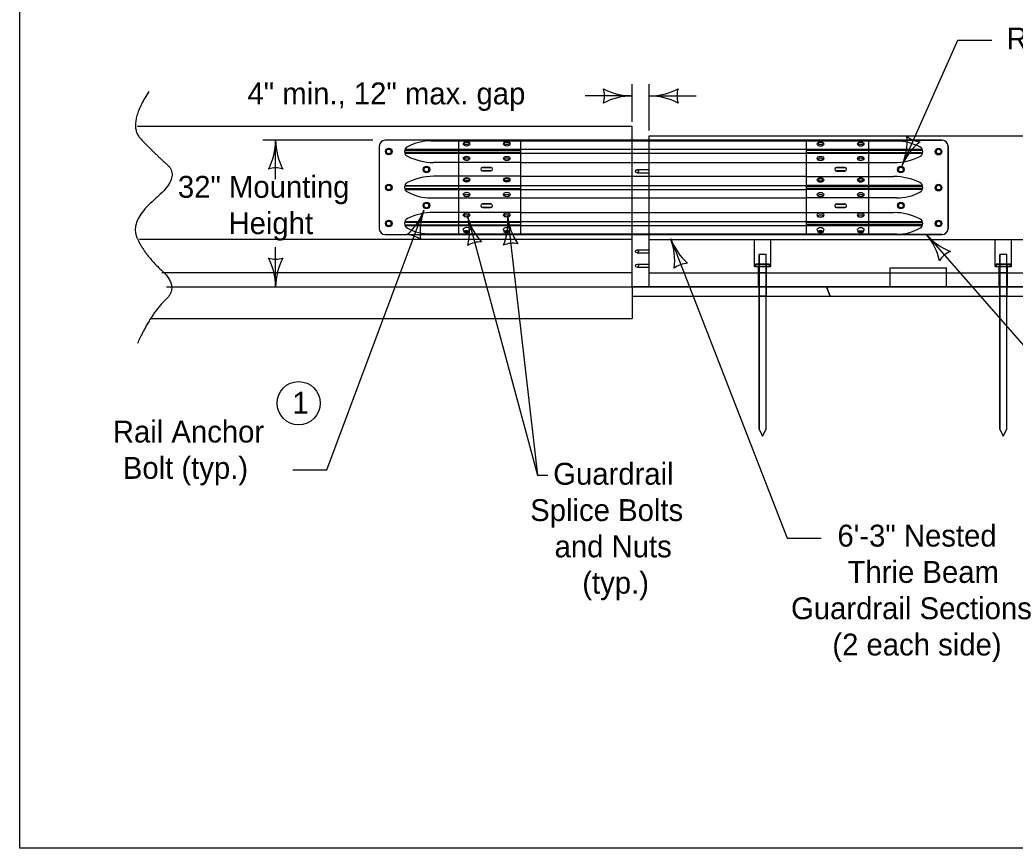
# Model space of a CAD drawing. Extents: x 10028 to 81668, y 3581 to 11018.
# Drawn here: x 13733 to 14423, y 7924 to 8499 of the extents above; entities that cross this region are included whole.
import ezdxf

# ---------------------------------------------------------------- set-up
doc = ezdxf.new("R2010")
doc.units = 0
for name, color, linetype in [('conPaving', 7, 'Continuous'), ('dsnCellsNorthArrow', 7, 'Continuous'), ('dsnTextTabulation', 7, 'Continuous'), ('Level 41', 7, 'Continuous'), ('Level 9', 7, 'Continuous'), ('SheetBorder', 7, 'Continuous')]:
    doc.layers.add(name, color=color, linetype=linetype)

msp = doc.modelspace()

# ---------------------------------------------------------------- linework, layer by layer
at = {"layer": 'conPaving'}
for p, q in [((14080.33, 8415.38), (13986.12, 8415.38)), ((14278.57, 8415.38), (14080.33, 8415.38)), ((14372.78, 8415.38), (14278.57, 8415.38)), ((13982.02, 8411.28), (13982.02, 8353.94)), ((14376.88, 8353.94), (14376.88, 8411.28)), ((14053.7, 8396.54), (14059.44, 8396.54)), ((14299.46, 8396.54), (14305.2, 8396.54)), ((14059.44, 8394.08), (14053.7, 8394.08)), ((14305.2, 8394.08), (14299.46, 8394.08)), ((14053.7, 8371.14), (14059.44, 8371.14)), ((14059.44, 8368.68), (14053.7, 8368.68)), ((14299.46, 8371.14), (14305.2, 8371.14)), ((14305.2, 8368.68), (14299.46, 8368.68)), ((13986.12, 8349.84), (14080.33, 8349.84)), ((14080.33, 8349.84), (14278.57, 8349.84)), ((14278.57, 8349.84), (14372.78, 8349.84)), ((14245.28, 8313.61), (14159.64, 8313.61)), ((14245.65, 8313.61), (14245.28, 8313.61)), ((14245.65, 8307.05), (14245.65, 8313.61)), ((14250.94, 8313.61), (14250.57, 8313.61)), ((14250.57, 8313.61), (14250.57, 8307.05)), ((14292.58, 8313.61), (14250.94, 8313.61)), ((14292.58, 8313.61), (14295.13, 8307.05)), ((14295.13, 8307.05), (14292.58, 8313.61)), ((14412.77, 8307.05), (14412.77, 8313.61)), ((14418.06, 8313.61), (14417.68, 8313.61)), ((14417.68, 8313.61), (14417.68, 8307.05)), ((14157.59, 8307.05), (14157.59, 8307.05)), ((14157.59, 8307.05), (14157.59, 8307.05)), ((14157.59, 8307.05), (14245.65, 8307.05)), ((14250.57, 8307.05), (14295.13, 8307.05)), ((14295.13, 8307.05), (14412.77, 8307.05)), ((14417.68, 8307.05), (14579.89, 8307.05))]:
    msp.add_line(p, q, dxfattribs=at)
for points in [[(14159.64, 8313.61), (14157.59, 8313.61), (14157.59, 8307.05)], [(14412.77, 8313.61), (14412.4, 8313.61), (14375.91, 8313.61), (14336.58, 8313.61), (14292.58, 8313.61)], [(14493.87, 8313.61), (14454.55, 8313.61), (14418.06, 8313.61)]]:
    msp.add_lwpolyline(points, dxfattribs=at)
for centre, radius, start, end in [((13986.12, 8411.28), 4.1, 90, 180), ((14372.78, 8411.28), 4.1, 0, 90), ((14053.7, 8395.31), 1.23, 90, 270), ((14059.44, 8395.31), 1.23, 270, 90), ((14299.46, 8395.31), 1.23, 90, 270), ((14305.2, 8395.31), 1.23, 270, 90), ((14053.7, 8369.91), 1.23, 90, 270), ((14059.44, 8369.91), 1.23, 270, 90), ((14299.46, 8369.91), 1.23, 90, 270), ((14305.2, 8369.91), 1.23, 270, 90), ((13986.12, 8353.94), 4.1, 180, 270), ((14372.78, 8353.94), 4.1, 270, 0)]:
    msp.add_arc(centre, radius, start, end, dxfattribs=at)
at = {"layer": 'dsnCellsNorthArrow'}
msp.add_line((14157.59, 8313.61), (14157.59, 8425.02), dxfattribs=at)
at = {"layer": 'dsnTextTabulation'}
for p, q in [((14344.94, 8397.87), (14383.72, 8484.78)), ((14383.72, 8484.78), (14407.32, 8484.78)), ((14157.59, 8428.24), (14157.59, 8454.2)), ((14169.47, 8422.14), (14169.47, 8454.2)), ((14157.59, 8446.16), (14125.02, 8446.16)), ((14169.47, 8446.16), (14202.03, 8446.16)), ((13977.54, 8415.38), (13901.17, 8415.38)), ((13910.06, 8388.43), (13910.06, 8415.38)), ((14169.47, 8313.85), (14169.47, 8418.46)), ((14169.47, 8418.46), (14660.99, 8418.46)), ((13945.69, 8186.49), (14013.03, 8366.86)), ((14043.27, 8362.89), (14091.8, 8182.83)), ((14071.11, 8362.89), (14091.8, 8182.83)), ((14169.47, 8346.37), (14660.99, 8346.37)), ((14184.39, 8346.97), (14265.14, 8139.23)), ((14361.76, 8350.15), (14525.96, 8161.81)), ((13910.06, 8313.61), (13910.06, 8341.06)), ((14336.58, 8326.71), (14375.91, 8326.71)), ((14169.47, 8323.44), (14660.99, 8323.44)), ((14336.58, 8313.61), (14336.58, 8323.44)), ((14375.91, 8313.61), (14375.91, 8323.44)), ((14169.71, 8313.61), (14336.58, 8313.61)), ((14375.91, 8313.61), (14454.55, 8313.61)), ((13922.09, 8186.49), (13945.69, 8186.49)), ((14091.8, 8182.83), (14099.09, 8182.83)), ((14265.14, 8139.23), (14288.74, 8139.23))]:
    msp.add_line(p, q, dxfattribs=at)
msp.add_circle((13926.02, 8232.83), 15, dxfattribs=at)
for centre, radius, start, end in [((14121.95, 8446.16), 16.42, 342.26665, 17.73335), ((14157.59, 8488.66), 42.5, 241.92751, 270), ((14121.95, 8446.16), 16.42, 342.26665, 17.73335), ((14157.59, 8488.66), 42.5, 241.92751, 270), ((14169.47, 8488.66), 42.5, 270, 298.07249), ((14169.47, 8488.66), 42.5, 270, 298.07249), ((14205.1, 8446.16), 16.42, 162.26665, 197.73335), ((14205.1, 8446.16), 16.42, 162.26665, 197.73335), ((14157.59, 8403.66), 42.5, 90, 118.07249), ((14157.59, 8403.66), 42.5, 90, 118.07249), ((14169.47, 8403.66), 42.5, 61.92751, 90), ((14169.47, 8403.66), 42.5, 61.92751, 90), ((13867.56, 8415.38), 42.5, 331.92751, 360), ((13952.56, 8415.38), 42.5, 180, 208.07249), ((14305.93, 8414.75), 42.5, 336.60184, 4.67433), ((14359.09, 8430.58), 16.42, 228.86849, 264.33519), ((14383.94, 8381), 42.5, 128.52935, 156.60184), ((13910.06, 8379.74), 16.42, 72.26665, 107.73335), ((13973.22, 8381.73), 42.5, 311.45357, 339.52606), ((14052.85, 8352), 42.5, 159.52606, 187.59855), ((14002.11, 8352.29), 42.5, 346.36285, 14.43534), ((14084.43, 8373.48), 42.5, 194.43534, 222.50783), ((14028.83, 8358.52), 42.5, 337.83385, 5.90634), ((14113.38, 8367.27), 42.5, 185.90634, 213.97883), ((14000.57, 8333.48), 16.42, 51.79271, 87.25941), ((14144.6, 8332.02), 42.5, 352.52075, 20.59324), ((14224.17, 8361.92), 42.5, 200.59324, 228.66573), ((14329.41, 8322.59), 42.5, 12.36113, 40.43362), ((14394.11, 8377.71), 42.5, 220.43362, 248.50611), ((14052.15, 8328.37), 16.42, 86.70199, 122.16869), ((14074.78, 8327.45), 16.42, 78.17299, 113.63969), ((13910.06, 8349.24), 16.42, 252.26665, 287.73335), ((13867.56, 8313.61), 42.5, 360, 28.07249), ((13952.56, 8313.61), 42.5, 151.92751, 180), ((14384.87, 8323.03), 16.42, 112.70027, 148.16697), ((14196.92, 8313.61), 16.42, 92.85989, 128.32659)]:
    msp.add_arc(centre, radius, start, end, dxfattribs=at)
at = {"layer": 'Level 41'}
for p, q in [((14160.96, 8394.95), (14169.47, 8394.95)), ((14160.96, 8392.83), (14169.47, 8392.83)), ((14242.45, 8327.81), (14242.45, 8346.37)), ((14253.77, 8327.81), (14253.77, 8346.37)), ((14409.56, 8327.81), (14409.56, 8346.37)), ((14420.89, 8327.81), (14420.89, 8346.37)), ((14160.96, 8339.24), (14169.46, 8339.24)), ((14160.96, 8337.12), (14169.46, 8337.12)), ((14160.96, 8329.41), (14169.46, 8329.41)), ((14160.96, 8327.29), (14169.46, 8327.29)), ((14242.45, 8327.81), (14253.77, 8327.81)), ((14245.28, 8313.61), (14245.28, 8327.81)), ((14250.94, 8313.61), (14250.94, 8327.81)), ((14409.56, 8327.81), (14420.89, 8327.81)), ((14412.4, 8313.61), (14412.4, 8327.81)), ((14418.06, 8313.61), (14418.06, 8327.81))]:
    msp.add_line(p, q, dxfattribs=at)
for centre in [(14160.96, 8393.89), (14160.96, 8338.18), (14160.96, 8328.35)]:
    msp.add_circle(centre, 1.06, dxfattribs=at)
at = {"layer": 'Level 9'}
for p, q in [((14157.59, 8425.02), (13814.19, 8425.02)), ((14080.33, 8415.38), (13986.12, 8415.38)), ((14080.33, 8415.38), (13986.12, 8415.38)), ((14036.91, 8415.38), (14036.91, 8349.84)), ((14080.33, 8349.84), (14080.33, 8415.38)), ((14278.57, 8415.38), (14372.78, 8415.38)), ((14278.57, 8349.84), (14278.57, 8415.38)), ((14321.99, 8349.73), (14321.99, 8415.27)), ((13982.02, 8411.28), (13982.02, 8353.94)), ((13982.02, 8411.28), (13982.02, 8353.94)), ((13999.63, 8408.46), (14080.33, 8408.46)), ((13999.86, 8409.08), (14080.33, 8409.08)), ((14359.04, 8408.96), (14278.57, 8408.96)), ((14359.26, 8408.35), (14278.57, 8408.35)), ((14376.88, 8411.28), (14376.88, 8353.94)), ((14376.88, 8411.28), (14376.88, 8353.94)), ((14080.33, 8406.93), (13999.56, 8406.93)), ((13999.73, 8406.32), (14080.33, 8406.32)), ((14278.57, 8406.82), (14359.33, 8406.82)), ((14359.17, 8406.21), (14278.57, 8406.21)), ((14080.33, 8383.38), (13999.56, 8383.38)), ((13999.63, 8381.84), (14080.33, 8381.84)), ((13999.73, 8383.99), (14080.33, 8383.99)), ((13999.86, 8381.23), (14080.33, 8381.23)), ((14359.17, 8383.88), (14278.57, 8383.88)), ((14278.57, 8383.27), (14359.33, 8383.27)), ((14359.26, 8381.73), (14278.57, 8381.73)), ((14359.04, 8381.12), (14278.57, 8381.12)), ((14080.33, 8358.29), (13999.56, 8358.29)), ((13999.63, 8356.76), (14080.33, 8356.76)), ((13999.73, 8358.91), (14080.33, 8358.91)), ((13999.86, 8356.15), (14080.33, 8356.15)), ((14359.17, 8358.79), (14278.57, 8358.79)), ((14278.57, 8358.18), (14359.33, 8358.18)), ((14359.26, 8356.65), (14278.57, 8356.65)), ((14359.04, 8356.04), (14278.57, 8356.04)), ((14157.59, 8346.37), (13815.45, 8346.37)), ((13986.12, 8349.84), (14080.33, 8349.84)), ((13986.12, 8349.84), (14080.33, 8349.84)), ((14080.33, 8349.84), (14278.57, 8349.84)), ((14080.33, 8349.84), (14278.57, 8349.84)), ((14372.78, 8349.84), (14278.57, 8349.84)), ((14250.57, 8336), (14245.65, 8336)), ((14245.65, 8336), (14245.65, 8329.45)), ((14250.57, 8336), (14245.65, 8336)), ((14245.65, 8214.76), (14245.65, 8336)), ((14250.57, 8329.45), (14250.57, 8336)), ((14250.57, 8214.76), (14250.57, 8336)), ((14417.68, 8336), (14412.77, 8336)), ((14412.77, 8336), (14412.77, 8329.45)), ((14417.68, 8336), (14412.77, 8336)), ((14412.77, 8214.76), (14412.77, 8336)), ((14417.68, 8329.45), (14417.68, 8336)), ((14417.68, 8214.76), (14417.68, 8336)), ((14243.19, 8329.45), (14243.19, 8327.81)), ((14245.65, 8329.45), (14243.19, 8329.45)), ((14243.19, 8327.81), (14243.19, 8329.45)), ((14243.19, 8327.81), (14245.28, 8327.81)), ((14245.28, 8327.81), (14245.65, 8327.81)), ((14250.57, 8329.45), (14245.65, 8329.45)), ((14245.65, 8329.45), (14245.65, 8327.81)), ((14245.65, 8327.81), (14245.65, 8329.45)), ((14245.65, 8329.45), (14250.57, 8329.45)), ((14250.57, 8327.81), (14245.65, 8327.81)), ((14245.65, 8327.81), (14245.65, 8323.44)), ((14245.65, 8327.81), (14250.57, 8327.81)), ((14250.57, 8327.81), (14250.57, 8329.45)), ((14250.57, 8329.45), (14250.57, 8327.81)), ((14250.57, 8323.44), (14250.57, 8327.81)), ((14336.58, 8323.44), (14336.58, 8326.71)), ((14375.91, 8323.44), (14375.91, 8326.71)), ((14410.31, 8329.45), (14410.31, 8327.81)), ((14412.77, 8329.45), (14410.31, 8329.45)), ((14410.31, 8327.81), (14410.31, 8329.45)), ((14410.31, 8327.81), (14412.4, 8327.81)), ((14412.4, 8327.81), (14412.77, 8327.81)), ((14417.68, 8329.45), (14412.77, 8329.45)), ((14412.77, 8329.45), (14412.77, 8327.81)), ((14412.77, 8327.81), (14412.77, 8329.45)), ((14412.77, 8329.45), (14417.68, 8329.45)), ((14417.68, 8327.81), (14412.77, 8327.81)), ((14412.77, 8327.81), (14412.77, 8323.44)), ((14412.77, 8327.81), (14417.68, 8327.81)), ((14417.68, 8327.81), (14417.68, 8329.45)), ((14417.68, 8329.45), (14417.68, 8327.81)), ((14417.68, 8323.44), (14417.68, 8327.81)), ((14157.59, 8323.44), (13831.11, 8323.44)), ((14250.57, 8323.44), (14245.65, 8323.44)), ((14245.65, 8323.44), (14245.65, 8313.61)), ((14245.65, 8323.44), (14250.57, 8323.44)), ((14250.57, 8313.61), (14250.57, 8323.44)), ((14336.58, 8323.44), (14375.91, 8323.44)), ((14417.68, 8323.44), (14412.77, 8323.44)), ((14412.77, 8323.44), (14412.77, 8313.61)), ((14412.77, 8323.44), (14417.68, 8323.44)), ((14417.68, 8313.61), (14417.68, 8323.44)), ((13834.39, 8313.61), (16709.19, 8313.61)), ((14157.59, 8313.61), (14157.59, 8307.05)), ((14157.59, 8313.61), (14157.59, 8291.66)), ((14169.47, 8313.85), (14169.71, 8313.61)), ((14250.57, 8313.61), (14245.65, 8313.61)), ((14245.65, 8313.61), (14245.65, 8307.05)), ((14245.65, 8313.61), (14250.57, 8313.61)), ((14250.57, 8307.05), (14250.57, 8313.61)), ((14417.68, 8313.61), (14412.77, 8313.61)), ((14412.77, 8313.61), (14412.77, 8307.05)), ((14412.77, 8313.61), (14417.68, 8313.61)), ((14417.68, 8307.05), (14417.68, 8313.61)), ((14157.59, 8307.05), (16177.13, 8307.05)), ((14250.57, 8307.05), (14245.65, 8307.05)), ((14245.65, 8307.05), (14245.65, 8214.76)), ((14245.65, 8307.05), (14250.57, 8307.05)), ((14250.57, 8214.76), (14250.57, 8307.05)), ((14417.68, 8307.05), (14412.77, 8307.05)), ((14412.77, 8307.05), (14412.77, 8214.76)), ((14412.77, 8307.05), (14417.68, 8307.05)), ((14417.68, 8214.76), (14417.68, 8307.05)), ((13823.32, 8291.66), (14157.59, 8291.66)), ((14245.65, 8214.76), (14248.11, 8209.84)), ((14245.65, 8214.76), (14248.11, 8209.84)), ((14248.11, 8209.84), (14250.57, 8214.76)), ((14248.11, 8209.84), (14250.57, 8214.76)), ((14412.77, 8214.76), (14415.23, 8209.84)), ((14412.77, 8214.76), (14415.23, 8209.84)), ((14415.23, 8209.84), (14417.68, 8214.76)), ((14415.23, 8209.84), (14417.68, 8214.76))]:
    msp.add_line(p, q, dxfattribs=at)
for points in [[(14080.33, 8415.38), (14278.57, 8415.38)], [(14017.92, 8414.88), (14080.33, 8414.88)], [(14080.33, 8414.88), (14278.57, 8414.88)], [(14080.33, 8409.08), (14278.57, 8409.08)], [(14340.98, 8414.77), (14278.57, 8414.77)], [(14080.33, 8406.32), (14278.57, 8406.32)], [(14080.33, 8399.97), (14019.55, 8399.97)], [(14059.44, 8396.54), (14053.7, 8396.54)], [(14059.44, 8396.54), (14053.7, 8396.54)], [(14080.33, 8399.97), (14278.57, 8399.97)], [(14278.57, 8399.86), (14339.35, 8399.86)], [(14299.46, 8396.43), (14305.2, 8396.43)], [(14305.2, 8396.43), (14299.46, 8396.43)], [(14299.46, 8396.43), (14305.2, 8396.43)], [(14305.2, 8396.43), (14299.46, 8396.43)], [(14080.33, 8390.34), (14019.55, 8390.34)], [(14053.7, 8394.08), (14059.44, 8394.08)], [(14053.7, 8394.08), (14059.44, 8394.08)], [(14080.33, 8390.34), (14278.57, 8390.34)], [(14278.57, 8390.23), (14339.35, 8390.23)], [(14305.2, 8393.97), (14299.46, 8393.97)], [(14299.46, 8393.97), (14305.2, 8393.97)], [(14305.2, 8393.97), (14299.46, 8393.97)], [(14299.46, 8393.97), (14305.2, 8393.97)], [(14080.33, 8383.99), (14278.57, 8383.99)], [(14080.33, 8381.23), (14278.57, 8381.23)], [(14017.92, 8375.42), (14080.33, 8375.42)], [(14080.33, 8375.42), (14278.57, 8375.42)], [(14340.98, 8375.31), (14278.57, 8375.31)], [(14059.44, 8371.14), (14053.7, 8371.14)], [(14059.44, 8371.14), (14053.7, 8371.14)], [(14053.7, 8368.68), (14059.44, 8368.68)], [(14053.7, 8368.68), (14059.44, 8368.68)], [(14299.46, 8371.03), (14305.2, 8371.03)], [(14305.2, 8371.03), (14299.46, 8371.03)], [(14299.46, 8371.03), (14305.2, 8371.03)], [(14305.2, 8371.03), (14299.46, 8371.03)], [(14305.2, 8368.57), (14299.46, 8368.57)], [(14299.46, 8368.57), (14305.2, 8368.57)], [(14305.2, 8368.57), (14299.46, 8368.57)], [(14299.46, 8368.57), (14305.2, 8368.57)], [(14080.33, 8365.26), (14019.55, 8365.26)], [(14080.33, 8365.26), (14278.57, 8365.26)], [(14278.57, 8365.14), (14339.35, 8365.14)], [(14080.33, 8358.91), (14278.57, 8358.91)], [(14080.33, 8356.15), (14278.57, 8356.15)], [(14017.92, 8350.34), (14080.33, 8350.34)], [(14080.33, 8350.34), (14278.57, 8350.34)], [(14340.98, 8350.23), (14278.57, 8350.23)], [(14243.19, 8329.45), (14253.03, 8329.45), (14253.03, 8327.81), (14243.19, 8327.81)], [(14253.03, 8327.81), (14253.03, 8329.45), (14250.57, 8329.45)], [(14250.57, 8327.81), (14250.94, 8327.81), (14253.03, 8327.81)], [(14410.31, 8329.45), (14420.14, 8329.45), (14420.14, 8327.81), (14410.31, 8327.81)], [(14420.14, 8327.81), (14420.14, 8329.45), (14417.68, 8329.45)], [(14417.68, 8327.81), (14418.06, 8327.81), (14420.14, 8327.81)]]:
    msp.add_lwpolyline(points, dxfattribs=at)
for centre, radius in [((13988.57, 8407.58), 2.3), ((13988.57, 8407.58), 1.64), ((13988.57, 8407.58), 1.64), ((14370.32, 8407.47), 2.3), ((14370.32, 8407.47), 1.64), ((14370.32, 8407.47), 1.64), ((14014.79, 8395.1), 2.3), ((14014.79, 8395.1), 1.64), ((14014.79, 8395.1), 1.64), ((14344.11, 8394.99), 2.3), ((14344.11, 8394.99), 1.64), ((14344.11, 8394.99), 1.64), ((13988.57, 8382.59), 2.3), ((13988.57, 8382.59), 1.64), ((13988.57, 8382.59), 1.64), ((14370.32, 8382.48), 2.3), ((14370.32, 8382.48), 1.64), ((14370.32, 8382.48), 1.64), ((14014.79, 8370.12), 2.3), ((14014.79, 8370.12), 1.64), ((14014.79, 8370.12), 1.64), ((14344.11, 8370.01), 2.3), ((14344.11, 8370.01), 1.64), ((14344.11, 8370.01), 1.64), ((13988.57, 8357.63), 2.3), ((13988.57, 8357.63), 1.64), ((13988.57, 8357.63), 1.64), ((14370.32, 8357.51), 2.3), ((14370.32, 8357.51), 1.64), ((14370.32, 8357.51), 1.64)]:
    msp.add_circle(centre, radius, dxfattribs=at)
for centre, radius, start, end in [((13986.12, 8411.28), 4.1, 90, 180), ((13986.12, 8411.28), 4.1, 90, 180), ((14372.78, 8411.28), 4.1, 0, 90), ((14372.78, 8411.28), 4.1, 0, 90), ((14003.1, 8407.53), 3.59, 113.8801, 246.1199), ((14017.45, 8382.18), 32.71, 89.18232, 118.89051), ((14341.45, 8382.07), 32.71, 61.10949, 90.81768), ((14355.8, 8407.42), 3.59, 293.8801, 66.1199), ((14019.51, 8439.34), 39.37, 243.01498, 270.05598), ((14339.38, 8439.23), 39.37, 269.94402, 296.98502), ((14053.7, 8395.31), 1.23, 90, 270), ((14053.7, 8395.31), 1.23, 90, 270), ((14059.44, 8395.31), 1.23, 270, 90), ((14059.44, 8395.31), 1.23, 270, 90), ((14299.46, 8395.2), 1.23, 90, 270), ((14299.46, 8395.2), 1.23, 90, 270), ((14299.46, 8395.2), 1.23, 90, 270), ((14299.46, 8395.2), 1.23, 90, 270), ((14305.2, 8395.2), 1.23, 270, 90), ((14305.2, 8395.2), 1.23, 270, 90), ((14305.2, 8395.2), 1.23, 270, 90), ((14305.2, 8395.2), 1.23, 270, 90), ((14019.51, 8350.97), 39.37, 89.94402, 116.98502), ((14339.38, 8350.86), 39.37, 63.01498, 90.05598), ((14003.1, 8382.77), 3.59, 113.8801, 246.1199), ((14355.8, 8382.66), 3.59, 293.8801, 66.1199), ((14017.45, 8408.13), 32.71, 241.10949, 270.81768), ((14341.45, 8408.02), 32.71, 269.18232, 298.89051), ((14053.7, 8369.91), 1.23, 90, 270), ((14053.7, 8369.91), 1.23, 90, 270), ((14059.44, 8369.91), 1.23, 270, 90), ((14059.44, 8369.91), 1.23, 270, 90), ((14299.46, 8369.8), 1.23, 90, 270), ((14299.46, 8369.8), 1.23, 90, 270), ((14299.46, 8369.8), 1.23, 90, 270), ((14299.46, 8369.8), 1.23, 90, 270), ((14305.2, 8369.8), 1.23, 270, 90), ((14305.2, 8369.8), 1.23, 270, 90), ((14305.2, 8369.8), 1.23, 270, 90), ((14305.2, 8369.8), 1.23, 270, 90), ((14003.1, 8357.69), 3.59, 113.8801, 246.1199), ((14019.51, 8325.88), 39.37, 89.94402, 116.98502), ((14339.38, 8325.77), 39.37, 63.01498, 90.05598), ((14355.8, 8357.58), 3.59, 293.8801, 66.1199), ((13986.12, 8353.94), 4.1, 180, 270), ((13986.12, 8353.94), 4.1, 180, 270), ((14017.45, 8383.04), 32.71, 241.10949, 270.81768), ((14341.45, 8382.93), 32.71, 269.18232, 298.89051), ((14372.78, 8353.94), 4.1, 270, 0), ((14372.78, 8353.94), 4.1, 270, 0)]:
    msp.add_arc(centre, radius, start, end, dxfattribs=at)
for centre, major_axis, ratio in [((14042.67, 8412.85), (-2.26, 0), 0.685714), ((14042.66, 8413.29), (-1.84, 0), 0.456281), ((14070.53, 8412.85), (-2.26, 0), 0.685714), ((14070.5, 8413.28), (-1.84, 0), 0.456281), ((14288.36, 8412.74), (2.26, 0), 0.685714), ((14288.4, 8413.17), (1.84, 0), 0.456281), ((14316.23, 8412.74), (2.26, 0), 0.685714), ((14316.24, 8413.18), (1.84, 0), 0.456281), ((14042.67, 8402.76), (-2.26, 0), 0.685714), ((14042.64, 8402.34), (-1.84, 0), 0.456281), ((14070.53, 8402.76), (-2.26, 0), 0.685714), ((14070.48, 8402.33), (-1.84, 0), 0.456281), ((14288.36, 8402.65), (2.26, 0), 0.685714), ((14288.42, 8402.22), (1.84, 0), 0.456281), ((14316.23, 8402.65), (2.26, 0), 0.685714), ((14316.26, 8402.23), (1.84, 0), 0.456281), ((14042.67, 8387.86), (-2.26, 0), 0.685714), ((14042.64, 8387.97), (-1.84, 0), 0.456281), ((14070.53, 8387.86), (-2.26, 0), 0.685714), ((14070.48, 8387.98), (-1.84, 0), 0.456281), ((14288.36, 8387.75), (2.26, 0), 0.685714), ((14288.42, 8387.87), (1.84, 0), 0.456281), ((14316.23, 8387.75), (2.26, 0), 0.685714), ((14316.26, 8387.86), (1.84, 0), 0.456281), ((14042.67, 8377.76), (-2.26, 0), 0.685714), ((14042.66, 8377.02), (-1.84, 0), 0.456281), ((14070.53, 8377.76), (-2.26, 0), 0.685714), ((14070.5, 8377.03), (-1.84, 0), 0.456281), ((14288.36, 8377.65), (2.26, 0), 0.685714), ((14288.4, 8376.92), (1.84, 0), 0.456281), ((14316.23, 8377.65), (2.26, 0), 0.685714), ((14316.24, 8376.91), (1.84, 0), 0.456281), ((14042.67, 8363.52), (-2.26, 0), 0.685714), ((14042.64, 8362.89), (-1.84, 0), 0.456281), ((14070.53, 8363.52), (-2.26, 0), 0.685714), ((14070.48, 8362.89), (-1.84, 0), 0.456281), ((14288.36, 8363.41), (2.26, 0), 0.685714), ((14288.42, 8362.78), (1.84, 0), 0.456281), ((14316.23, 8363.41), (2.26, 0), 0.685714), ((14316.26, 8362.78), (1.84, 0), 0.456281), ((14042.67, 8353.42), (-2.26, 0), 0.685714), ((14070.53, 8353.42), (-2.26, 0), 0.685714), ((14288.36, 8353.31), (2.26, 0), 0.685714), ((14316.23, 8353.31), (2.26, 0), 0.685714), ((14042.66, 8351.93), (-1.84, 0), 0.456281), ((14070.5, 8351.94), (-1.84, 0), 0.456281), ((14288.4, 8351.83), (1.84, 0), 0.456281), ((14316.24, 8351.82), (1.84, 0), 0.456281)]:
    msp.add_ellipse(centre, major_axis=major_axis, ratio=ratio, dxfattribs=at)
msp.add_open_spline([(13822.07, 8449.28), (13806.99, 8426.2), (13825.62, 8406.67), (13844.26, 8389.8), (13808.76, 8359.61), (13818.52, 8336.52), (13843.37, 8313.44), (13823.85, 8295.68), (13814.09, 8274.37)], degree=2, dxfattribs=at)
at = {"layer": 'SheetBorder'}
msp.add_lwpolyline([(13732.52, 9944.02), (16867.53, 9944.02), (16867.53, 7924.02), (13732.52, 7924.02)], close=True, dxfattribs=at)

# ---------------------------------------------------------------- texts
at = {"layer": 'dsnCellsNorthArrow'}
for s, p in [('Rail Anchor Bolt', (14417.45, 8478.43)), ('4" min., 12" max. gap', (13890.49, 8440.26)), ('32" Mounting', (13842.21, 8375.43)), ('Height', (13877.32, 8350.23)), ('Rail Anchor', (13797.03, 8205.53)), ('Bolt (typ.)', (13803.98, 8180.33)), ('Guardrail', (14102.76, 8176.24)), ('Splice Bolts', (14086.79, 8151.04)), ('6\'-3" Nested', (14300.09, 8133.31)), ('and Nuts', (14103.7, 8125.84)), ('Thrie Beam', (14307.13, 8108.11)), ('(typ.)', (14122.93, 8100.64)), ('Guardrail Sections', (14267.87, 8082.91)), ('(2 each side)', (14296.55, 8057.71))]:
    msp.add_text(s, height=15.2, dxfattribs=at).set_placement(p)
at = {"layer": 'dsnTextTabulation'}
msp.add_text('1', height=15.2, dxfattribs=at).set_placement((13921.65, 8225.54))

doc.saveas('drawing.dxf')
